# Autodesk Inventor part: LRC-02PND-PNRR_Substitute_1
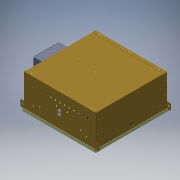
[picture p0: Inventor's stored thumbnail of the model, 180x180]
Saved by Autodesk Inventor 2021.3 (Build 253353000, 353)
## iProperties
Part Number: LRC-02PND-PNRR_Substitute_1
Material: Generic
Document SubType Name: Modeling
Designer: JChurch
Manufacturer: Standard
Standards Organization: Custom
Density: 1 g/cm^3
Appearance: Smooth - Black
Author: JChurch
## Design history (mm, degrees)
derived "LRC-02PND-PNRR.iam"
body "Solid9"
node "830520-00-00.ipt:1"
node "881088-00-00.iam:1::830140-00-00.ipt:1"
body "Solid10"
node "881088-00-00.iam:1::850014-00-00.iam:1::805044-00-00.ipt:1"
body "Solid11"
node "881088-00-00.iam:1::850014-00-00.iam:1::805174-00-00.ipt:1"
body "Solid12"
node "881088-00-00.iam:1::850014-00-00.iam:1::502055-00-00.ipt:1"
body "Solid13"
node "881088-00-00.iam:1::850014-00-00.iam:1::502055-00-00.ipt:2"
body "Solid14"
node "881088-00-00.iam:1::850014-00-00.iam:1::507032-00-00.ipt:1"
body "Solid15"
node "881088-00-00.iam:1::507000-00-00.ipt:1"
body "Solid16"
node "881088-00-00.iam:1::507000-00-00.ipt:2"
body "Solid17"
node "881088-00-00.iam:1::506002-00-00.ipt:1"
body "Solid18"
node "881088-00-00.iam:1::506002-00-00.ipt:2"
body "Solid19"
node "881088-00-00.iam:1::506002-00-00.ipt:3"
body "Solid20"
node "881088-00-00.iam:1::506002-00-00.ipt:4"
body "Solid21"
node "881088-00-00.iam:1::506002-00-00.ipt:5"
body "Solid22"
node "881088-00-00.iam:1::506002-00-00.ipt:6"
body "Solid23"
node "881088-00-00.iam:1::506002-00-00.ipt:7"
body "Solid24"
node "881088-00-00.iam:1::506002-00-00.ipt:8"
body "Solid25"
node "881088-00-00.iam:1::506002-00-00.ipt:9"
body "Solid26"
node "881088-00-00.iam:1::506002-00-00.ipt:10"
body "Solid27"
node "881088-00-00.iam:1::506002-00-00.ipt:11"
body "Solid28"
node "881088-00-00.iam:1::506002-00-00.ipt:12"
body "Solid29"
node "881088-00-00.iam:1::506002-00-00.ipt:13"
body "Solid30"
node "881088-00-00.iam:1::506002-00-00.ipt:14"
body "Solid31"
node "881088-00-00.iam:1::830392-01-00.iam:1::830392-00-00.ipt:1"
body "Solid32"
node "881088-00-00.iam:1::830392-01-00.iam:1::500027-00-00.ipt:1"
body "Solid33"
node "881088-00-00.iam:1::830392-01-00.iam:1::501030-00-00.ipt:1"
body "Solid34"
node "881088-00-00.iam:1::830392-01-00.iam:1::500027-00-00.ipt:2"
body "Solid35"
node "881088-00-00.iam:1::830392-01-00.iam:1::501030-00-00.ipt:2"
body "Solid36"
node "881088-00-00.iam:1::830392-01-00.iam:1::501030-00-00.ipt:3"
body "Solid37"
node "881088-00-00.iam:1::830392-01-00.iam:1::501030-00-00.ipt:4"
body "Solid38"
node "881088-00-00.iam:1::830392-01-00.iam:2::830392-00-00.ipt:1"
body "Solid39"
node "881088-00-00.iam:1::830392-01-00.iam:2::500027-00-00.ipt:1"
body "Solid40"
node "881088-00-00.iam:1::830392-01-00.iam:2::501030-00-00.ipt:1"
body "Solid41"
node "881088-00-00.iam:1::830392-01-00.iam:2::500027-00-00.ipt:2"
body "Solid42"
node "881088-00-00.iam:1::830392-01-00.iam:2::501030-00-00.ipt:2"
body "Solid43"
node "881088-00-00.iam:1::830392-01-00.iam:2::501030-00-00.ipt:3"
body "Solid44"
node "881088-00-00.iam:1::830392-01-00.iam:2::501030-00-00.ipt:4"
body "Solid45"
node "750453-02-XX.iam:1::740102-00-XX.ipt:1"
body "Solid46"
node "750453-02-XX.iam:1::507035-01-38.ipt:1"
body "Solid47"
node "750453-02-XX.iam:1::507035-01-38.ipt:2"
body "Solid48"
node "750453-02-XX.iam:1::510048-00-00_4.16_DIA_NEW.ipt:1"
body "Solid49"
node "750453-02-XX.iam:1::700496-01-XX.ipt:1"
body "Solid50"
other parameters: "d15" = 61.595, "d16" = 9.525, "d17" = 9.525, "d35" = 5.08
